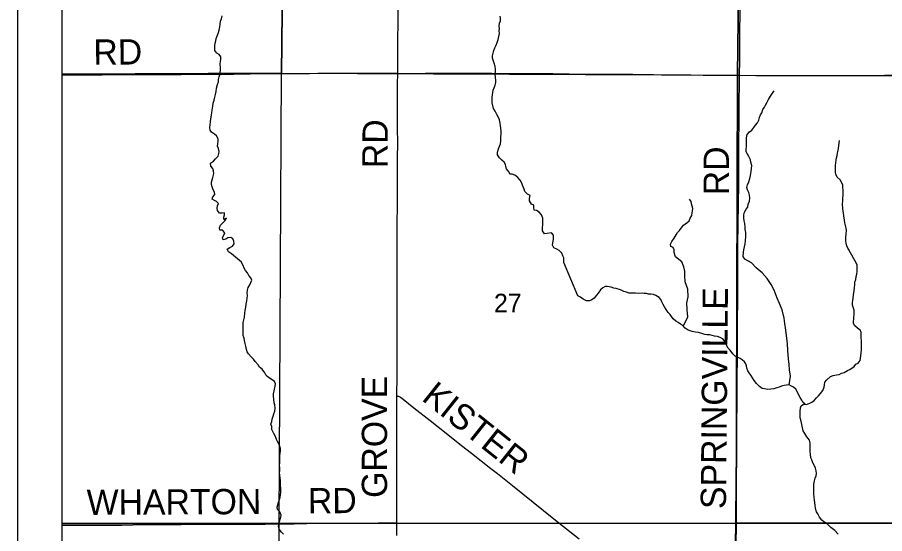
# Model space of a CAD drawing. Extents: x 0 to 34, y 0 to 22.
# Drawn here: x 2 to 3.95, y 16.861 to 18.022 of the extents above; entities that cross this region are included whole.
import ezdxf

# ---------------------------------------------------------------- set-up
doc = ezdxf.new("R2010")
doc.units = 0
for name, color, linetype in [('Default', 7, 'Continuous'), ('GM_X_County_Road', 7, 'Continuous'), ('GM_X_County_Road_Text', 7, 'Continuous'), ('GM_X_Minor_River', 7, 'Continuous'), ('GM_X_Section', 7, 'Continuous'), ('GM_X_Section_Text', 7, 'Continuous'), ('GM_X_State_Route', 7, 'Continuous'), ('GM_X_Township_Road', 7, 'Continuous'), ('GM_X_Township_Road_Text', 7, 'Continuous'), ('SH_Data', 7, 'Continuous')]:
    doc.layers.add(name, color=color, linetype=linetype)

msp = doc.modelspace()

# ---------------------------------------------------------------- linework, layer by layer
at = {"layer": 'Default'}
for points in [[(2.4548, 18.9153), (2.1, 18.9091), (2.1, 17.8937), (2.5938, 17.8965), (2.6002, 18.514), (2.4548, 18.514)], [(2.1, 17.8937), (2.1, 16.8844), (2.5888, 16.8843), (2.5938, 17.8965)], [(2.1, 16.8844), (2.1, 15.87), (2.5857, 15.8713), (2.5888, 16.8843)]]:
    msp.add_lwpolyline(points, close=True, dxfattribs=at)
at = {"layer": 'GM_X_County_Road'}
for points in [[(2.855, 17.896), (2.8551, 17.9234), (2.8554, 17.9703), (2.8559, 18.0107), (2.8562, 18.1102), (2.8563, 18.1288), (2.8567, 18.1597), (2.8569, 18.1752), (2.8573, 18.2095), (2.8578, 18.2498), (2.8579, 18.2683), (2.8581, 18.2828), (2.8581, 18.3026), (2.8579, 18.3181), (2.8579, 18.3492), (2.8581, 18.3742), (2.8598, 18.4422), (2.8601, 18.4603), (2.8603, 18.4764), (2.8608, 18.514)], [(2.8534, 17.1706), (2.8534, 17.1785), (2.8538, 17.2095), (2.8536, 17.225), (2.8536, 17.2581), (2.8535, 17.3023), (2.8537, 17.3672), (2.8538, 17.3924), (2.8537, 17.4546), (2.8539, 17.4856), (2.8538, 17.5355), (2.8539, 17.554), (2.8542, 17.6036), (2.8543, 17.6379), (2.8544, 17.6557), (2.8545, 17.675), (2.8547, 17.7057), (2.855, 17.7383), (2.8549, 17.7739), (2.8548, 17.7959), (2.8548, 17.8179), (2.8548, 17.8521), (2.8549, 17.8708), (2.855, 17.896)], [(2.853, 16.8858), (2.853, 16.8915), (2.853, 16.9299), (2.8532, 16.9549), (2.8531, 16.989), (2.8531, 17.0199), (2.8529, 17.0697), (2.8531, 17.1255), (2.8534, 17.1706)], [(2.853, 16.8571), (2.8531, 16.8789), (2.853, 16.8858)]]:
    msp.add_lwpolyline(points, dxfattribs=at)
at = {"layer": 'GM_X_Minor_River'}
for points in [[(2.4519, 17.9879), (2.4538, 17.9928), (2.4553, 18.0008), (2.4556, 18.0065), (2.4564, 18.013), (2.4586, 18.0183), (2.4601, 18.0248)], [(3.2281, 17.4709), (3.2285, 17.4751), (3.2281, 17.4812), (3.2261, 17.4861), (3.2242, 17.4918), (3.2181, 17.4979), (3.2124, 17.5005), (3.2059, 17.5035), (3.2032, 17.51), (3.2036, 17.5149), (3.2051, 17.5225), (3.205, 17.5324), (3.2008, 17.5373), (3.1913, 17.5358), (3.1853, 17.535), (3.1807, 17.5418), (3.1803, 17.5498), (3.1814, 17.5555), (3.1813, 17.565), (3.1809, 17.5703), (3.1782, 17.5783), (3.1729, 17.584), (3.1668, 17.5877), (3.1618, 17.5885), (3.1611, 17.5942), (3.161, 17.5999), (3.1561, 17.6018), (3.1511, 17.6097), (3.1511, 17.615), (3.1529, 17.6211), (3.1469, 17.6241), (3.1411, 17.6302), (3.1396, 17.6359), (3.1369, 17.6412), (3.1334, 17.6503), (3.13, 17.656), (3.125, 17.6617), (3.1185, 17.667), (3.1121, 17.6692), (3.1068, 17.6692), (3.1056, 17.6741), (3.0999, 17.6813), (3.0983, 17.6863), (3.0972, 17.6912), (3.0941, 17.6961), (3.0888, 17.7007), (3.0838, 17.7064), (3.0796, 17.7128), (3.0796, 17.7189), (3.0818, 17.7261), (3.0863, 17.7376), (3.0866, 17.744), (3.087, 17.7528), (3.0873, 17.7608), (3.0873, 17.7661), (3.0869, 17.7725), (3.0861, 17.7779), (3.0853, 17.7836), (3.0837, 17.7912), (3.0814, 17.7968), (3.078, 17.8037), (3.0741, 17.8109), (3.0703, 17.8169), (3.0672, 17.8299), (3.0672, 17.8352), (3.0675, 17.8424), (3.069, 17.8531), (3.0697, 17.858), (3.072, 17.8633), (3.0738, 17.8694), (3.0753, 17.8751), (3.0753, 17.8801), (3.0745, 17.8877), (3.0741, 17.8938), (3.0748, 17.9006), (3.0748, 17.9056), (3.0744, 17.9113), (3.0721, 17.9185), (3.0682, 17.9299), (3.0682, 17.9356), (3.0693, 17.9413), (3.0711, 17.9474), (3.073, 17.9531), (3.076, 17.9592), (3.0786, 17.9653), (3.0805, 17.9721), (3.082, 17.9786), (3.0835, 17.9858), (3.0834, 17.9915), (3.0838, 17.9968), (3.0834, 18.0022), (3.0841, 18.009), (3.086, 18.014), (3.086, 18.0189), (3.0855, 18.0246)], [(2.5037, 17.4713), (2.4811, 17.4903), (2.4743, 17.4949), (2.4716, 17.5006), (2.478, 17.5048), (2.4833, 17.5074), (2.4875, 17.5124), (2.487, 17.5189), (2.4847, 17.5242), (2.4798, 17.5268), (2.4733, 17.526), (2.4684, 17.5233), (2.4627, 17.5214), (2.4608, 17.5264), (2.4661, 17.5378), (2.4611, 17.5435), (2.455, 17.5434), (2.4542, 17.5484), (2.4565, 17.5545), (2.4614, 17.5591), (2.4667, 17.5648), (2.4701, 17.5701), (2.464, 17.5678), (2.464, 17.5728), (2.4655, 17.5777), (2.4658, 17.5827), (2.4601, 17.5819), (2.4545, 17.5815), (2.4499, 17.5875), (2.4491, 17.5928), (2.4498, 17.5982), (2.4521, 17.6031), (2.4479, 17.608), (2.4429, 17.6103), (2.438, 17.6129), (2.4391, 17.6183), (2.4436, 17.6236), (2.4428, 17.6289), (2.4401, 17.6339), (2.4378, 17.6407), (2.4363, 17.646), (2.4366, 17.6517), (2.4381, 17.6567), (2.4392, 17.662), (2.4415, 17.6708), (2.441, 17.6765), (2.4395, 17.6818), (2.4353, 17.6871), (2.4341, 17.6939), (2.4409, 17.6989), (2.4451, 17.7038), (2.4511, 17.71), (2.453, 17.7157), (2.4533, 17.7206), (2.4522, 17.7267), (2.4502, 17.7324), (2.451, 17.7377), (2.4513, 17.7438), (2.4513, 17.7491), (2.4478, 17.7552), (2.4429, 17.759), (2.4368, 17.7635), (2.4334, 17.7684), (2.4326, 17.7745), (2.4333, 17.7802), (2.4344, 17.7874), (2.4355, 17.7981), (2.4369, 17.8072), (2.4377, 17.8133), (2.4391, 17.8221), (2.4402, 17.8289), (2.4425, 17.8354), (2.4436, 17.8422), (2.4455, 17.8483), (2.4469, 17.8548), (2.448, 17.8628), (2.4499, 17.8712), (2.4518, 17.8769), (2.4525, 17.8822), (2.454, 17.8879), (2.4555, 17.8929), (2.4562, 17.8978), (2.4569, 17.9031), (2.4569, 17.9088), (2.4561, 17.9168), (2.4565, 17.9225), (2.4576, 17.9275), (2.4575, 17.9328), (2.4533, 17.9381), (2.4484, 17.9415), (2.4442, 17.9472), (2.4438, 17.9536), (2.4441, 17.9586), (2.4448, 17.9639), (2.446, 17.9692), (2.4471, 17.9742), (2.4501, 17.9814), (2.4519, 17.9879)], [(3.6506, 17.4701), (3.6355, 17.4782), (3.6318, 17.4842), (3.6322, 17.4937), (3.6333, 17.499), (3.6344, 17.5059), (3.6359, 17.5127), (3.6366, 17.5199), (3.6373, 17.5287), (3.6372, 17.5382), (3.6364, 17.5458), (3.636, 17.5507), (3.6352, 17.5587), (3.6341, 17.5648), (3.6329, 17.5712), (3.6332, 17.5777), (3.6347, 17.5842), (3.6381, 17.5903), (3.6419, 17.5952), (3.643, 17.6017), (3.646, 17.6089), (3.6463, 17.6162), (3.6455, 17.6219), (3.644, 17.6279), (3.6413, 17.6344), (3.6401, 17.6397), (3.6416, 17.645), (3.6442, 17.6523), (3.6465, 17.6595), (3.648, 17.666), (3.6498, 17.6755), (3.6505, 17.682), (3.6509, 17.6888), (3.6489, 17.696), (3.6478, 17.7013), (3.6443, 17.7089), (3.6416, 17.7146), (3.6386, 17.7196), (3.6385, 17.726), (3.6389, 17.731), (3.6392, 17.7363), (3.6392, 17.7511), (3.6403, 17.7587), (3.6459, 17.7648), (3.6508, 17.7683), (3.6557, 17.774), (3.6591, 17.7797), (3.6637, 17.7847), (3.6667, 17.7904), (3.6681, 17.7969), (3.6704, 17.8026), (3.6734, 17.8075), (3.6756, 17.8144), (3.6798, 17.8197), (3.6817, 17.8247), (3.6858, 17.8312), (3.6884, 17.8373), (3.6933, 17.8445), (3.6975, 17.8514), (3.7012, 17.8567)], [(3.8698, 17.4978), (3.8697, 17.4982), (3.867, 17.5031), (3.8647, 17.5081), (3.8632, 17.5134), (3.862, 17.5198), (3.8624, 17.5271), (3.8634, 17.535), (3.8638, 17.5426), (3.863, 17.5483), (3.8615, 17.554), (3.8603, 17.5597), (3.8591, 17.5658), (3.8575, 17.5757), (3.8571, 17.5814), (3.856, 17.5863), (3.8552, 17.592), (3.8551, 17.6027), (3.8555, 17.6088), (3.8558, 17.6152), (3.8562, 17.6225), (3.8561, 17.6335), (3.8557, 17.6392), (3.8557, 17.6445), (3.8534, 17.6498), (3.8495, 17.6566), (3.8427, 17.6627), (3.84, 17.6691), (3.8392, 17.6741), (3.8388, 17.6824), (3.8391, 17.6885), (3.8398, 17.6946), (3.8409, 17.7011), (3.8417, 17.706), (3.8428, 17.7114), (3.8435, 17.7163), (3.8461, 17.7273), (3.8476, 17.7395), (3.8483, 17.7452)], [(3.4797, 17.4836), (3.4762, 17.4933), (3.4762, 17.499), (3.4739, 17.5044), (3.4689, 17.507), (3.4685, 17.5123), (3.4711, 17.518), (3.4768, 17.5257), (3.4809, 17.5329), (3.4839, 17.5379), (3.4881, 17.5428), (3.4918, 17.5478), (3.4975, 17.5547), (3.5051, 17.56), (3.51, 17.5642), (3.5126, 17.5703), (3.516, 17.5768), (3.5171, 17.5821), (3.5174, 17.5871), (3.5182, 17.592), (3.517, 17.5977), (3.5155, 17.6026), (3.5143, 17.608), (3.5109, 17.6133)], [(3.8826, 17.4211), (3.8826, 17.4268), (3.8845, 17.4329), (3.8856, 17.4397), (3.8871, 17.4447), (3.8875, 17.4504), (3.8875, 17.4569), (3.8878, 17.4648), (3.8859, 17.4698), (3.8698, 17.4978)], [(2.5503, 17.231), (2.5446, 17.2352), (2.5412, 17.2405), (2.5347, 17.2485), (2.5308, 17.2534), (2.5259, 17.2588), (2.5197, 17.2652), (2.5167, 17.2702), (2.5151, 17.2755), (2.5136, 17.2827), (2.5124, 17.2888), (2.5109, 17.2957), (2.5097, 17.3006), (2.5078, 17.3067), (2.5078, 17.312), (2.5074, 17.3223), (2.5074, 17.3363), (2.5092, 17.342), (2.5104, 17.3477), (2.5115, 17.3569), (2.5123, 17.3626), (2.5134, 17.3706), (2.5145, 17.3774), (2.516, 17.3846), (2.5168, 17.3907), (2.5171, 17.3968), (2.5167, 17.4025), (2.5171, 17.4086), (2.519, 17.4147), (2.5224, 17.4208), (2.5251, 17.4257), (2.527, 17.431), (2.5251, 17.4363), (2.5201, 17.4413), (2.5174, 17.4478), (2.5128, 17.4531), (2.5101, 17.4584), (2.5078, 17.4637), (2.5047, 17.4694), (2.5037, 17.4713)], [(3.7709, 17.1521), (3.766, 17.1569), (3.7634, 17.1615), (3.7595, 17.1675), (3.7553, 17.1759), (3.7526, 17.1809), (3.7496, 17.1858), (3.7446, 17.1904), (3.74, 17.193), (3.7347, 17.1961), (3.7289, 17.1949), (3.7236, 17.1942), (3.7175, 17.193), (3.7125, 17.1908), (3.7072, 17.1889), (3.7007, 17.187), (3.6935, 17.1858), (3.687, 17.1855), (3.6793, 17.1866), (3.674, 17.1877), (3.6683, 17.1919), (3.6618, 17.1992), (3.6564, 17.2056), (3.6522, 17.2113), (3.6484, 17.2174), (3.6453, 17.2231), (3.6422, 17.2277), (3.6399, 17.233), (3.6388, 17.2383), (3.6376, 17.2429), (3.6349, 17.2479), (3.6296, 17.2524), (3.6246, 17.2547), (3.6189, 17.2577), (3.6139, 17.2604), (3.6086, 17.2657), (3.602, 17.2737), (3.5978, 17.2783), (3.5948, 17.2832), (3.5925, 17.2882), (3.5909, 17.2927), (3.5856, 17.2996), (3.5798, 17.3026), (3.5737, 17.3042), (3.5669, 17.3053), (3.5619, 17.3068), (3.5569, 17.308), (3.5501, 17.3084), (3.5455, 17.3091), (3.539, 17.311), (3.5314, 17.3133), (3.5241, 17.3145), (3.5172, 17.316), (3.5126, 17.3171), (3.5077, 17.3187), (3.5012, 17.3232), (3.4962, 17.3293), (3.4905, 17.3324), (3.4851, 17.3358), (3.4802, 17.3392), (3.4744, 17.3441), (3.4702, 17.3491), (3.4671, 17.3537), (3.4626, 17.3586), (3.4583, 17.3655), (3.4545, 17.3712), (3.4514, 17.3765), (3.4484, 17.3822), (3.4465, 17.3875), (3.4426, 17.3921), (3.4354, 17.397), (3.43, 17.3989), (3.4239, 17.3997), (3.4189, 17.3997), (3.4144, 17.4008), (3.409, 17.4008), (3.4044, 17.4016), (3.3953, 17.4012), (3.3892, 17.4016), (3.3754, 17.4016), (3.3693, 17.4043), (3.3636, 17.4058), (3.3556, 17.4092), (3.346, 17.4123), (3.3411, 17.4131), (3.3346, 17.415), (3.3262, 17.4172), (3.3212, 17.4169), (3.3159, 17.4142), (3.3109, 17.4096), (3.3056, 17.402), (3.3018, 17.3971), (3.2965, 17.391), (3.2911, 17.3872), (3.2858, 17.3849), (3.2797, 17.3846), (3.272, 17.3884), (3.2659, 17.3929), (3.2598, 17.396), (3.2281, 17.4709)], [(3.4972, 17.3281), (3.5068, 17.349), (3.5056, 17.3641), (3.5048, 17.3805), (3.5077, 17.3938), (3.5073, 17.4108), (3.5012, 17.4271), (3.5007, 17.4408), (3.5003, 17.451), (3.498, 17.4609), (3.4938, 17.4723), (3.4797, 17.4836)], [(3.7347, 17.1961), (3.738, 17.215), (3.736, 17.2298), (3.7348, 17.2412), (3.7333, 17.2541), (3.7317, 17.2734), (3.7309, 17.2886), (3.7297, 17.3), (3.7273, 17.3186), (3.7254, 17.3337), (3.7234, 17.3459), (3.7192, 17.3645), (3.7135, 17.3785), (3.7077, 17.3906), (3.7009, 17.4088), (3.6944, 17.4213), (3.6852, 17.4346), (3.6742, 17.4474), (3.6609, 17.4588), (3.6506, 17.4701)], [(3.8454, 16.8606), (3.8373, 16.8682), (3.8285, 16.8755), (3.8213, 16.8827), (3.8132, 16.8876), (3.8083, 16.8918), (3.8033, 16.8987), (3.7995, 16.9059), (3.7964, 16.9105), (3.7941, 16.9177), (3.7933, 16.9257), (3.7921, 16.9367), (3.7914, 16.9424), (3.7906, 16.9519), (3.7902, 16.9607), (3.7902, 16.9664), (3.7905, 16.9725), (3.792, 16.9801), (3.7935, 16.9861), (3.7954, 16.9911), (3.7962, 16.9968), (3.7958, 17.0029), (3.7939, 17.0086), (3.7916, 17.0139), (3.7885, 17.0207), (3.7862, 17.0272), (3.7839, 17.0318), (3.7831, 17.0398), (3.7823, 17.0462), (3.7819, 17.0535), (3.7819, 17.0656), (3.7808, 17.0713), (3.775, 17.0789), (3.77, 17.0862), (3.7662, 17.0923), (3.7639, 17.1033), (3.7619, 17.1139), (3.76, 17.1219), (3.7596, 17.1272), (3.7596, 17.136), (3.7607, 17.1443), (3.7619, 17.1489), (3.7672, 17.1523), (3.7737, 17.1519), (3.7813, 17.155), (3.7859, 17.1569), (3.7908, 17.1603), (3.7962, 17.1664), (3.8011, 17.1713), (3.8057, 17.1766), (3.8103, 17.1835), (3.8133, 17.1907), (3.814, 17.196), (3.8152, 17.2021), (3.8186, 17.2067), (3.8281, 17.2147), (3.8335, 17.2169), (3.8415, 17.2185), (3.8472, 17.2192), (3.8525, 17.2219), (3.8586, 17.2234), (3.8659, 17.2283), (3.8712, 17.2302), (3.8807, 17.2371), (3.8849, 17.2424), (3.8902, 17.2447), (3.8944, 17.2508), (3.8952, 17.2557), (3.8959, 17.2614), (3.8967, 17.2679), (3.8974, 17.2743), (3.8978, 17.2816), (3.8974, 17.2888), (3.8978, 17.296), (3.897, 17.3009), (3.897, 17.3139), (3.8947, 17.3184), (3.8889, 17.323), (3.8828, 17.3283), (3.8797, 17.334), (3.8797, 17.3386), (3.8805, 17.3435), (3.8805, 17.3485), (3.8808, 17.353), (3.8808, 17.3633), (3.8773, 17.3751), (3.8773, 17.3808), (3.8777, 17.3854), (3.8785, 17.3903), (3.8792, 17.3987), (3.8811, 17.407), (3.8818, 17.4135), (3.8826, 17.4211)], [(2.5982, 16.8602), (2.594, 16.8651), (2.5886, 16.8712), (2.5874, 16.8773), (2.5886, 16.8868), (2.5924, 16.8982), (2.5931, 16.9032), (2.5897, 16.9108), (2.5851, 16.9157), (2.5843, 16.9207), (2.5854, 16.9264), (2.5869, 16.9321), (2.5892, 16.9378), (2.5907, 16.9431), (2.5915, 16.948), (2.5926, 16.9545), (2.5922, 16.9636), (2.5918, 16.9693), (2.5914, 16.9758), (2.5918, 16.9811), (2.5906, 16.9872), (2.5898, 16.9925), (2.5895, 16.9979), (2.5902, 17.0028), (2.5898, 17.0089), (2.589, 17.0153), (2.5898, 17.0203), (2.5901, 17.0279), (2.5897, 17.0363), (2.5905, 17.0423), (2.5916, 17.0477), (2.5912, 17.053), (2.5882, 17.0621), (2.5847, 17.0682), (2.5824, 17.0732), (2.5801, 17.0796), (2.5763, 17.0868), (2.5724, 17.0956), (2.572, 17.1021), (2.5701, 17.1074), (2.572, 17.1135), (2.5731, 17.1184), (2.5754, 17.1256), (2.5765, 17.1306), (2.5788, 17.137), (2.5796, 17.1431), (2.5788, 17.1507), (2.5772, 17.1557), (2.5768, 17.1637), (2.5761, 17.1701), (2.5757, 17.1758), (2.5772, 17.1823), (2.5794, 17.1926), (2.5802, 17.1983), (2.5783, 17.2032), (2.5725, 17.207), (2.5645, 17.2127), (2.5595, 17.2165), (2.5565, 17.2226), (2.5503, 17.231)]]:
    msp.add_lwpolyline(points, dxfattribs=at)
at = {"layer": 'GM_X_Section'}
for points in [[(2.6002, 18.514), (2.5938, 17.8965), (3.6191, 17.892), (3.6261, 18.514)], [(3.6261, 18.514), (3.6191, 17.892), (4.6321, 17.8882), (4.6433, 18.514)], [(2.5938, 17.8965), (3.6191, 17.892), (3.6155, 16.8848), (2.5888, 16.8843)], [(3.6191, 17.892), (4.6321, 17.8882), (4.6282, 16.8848), (3.6155, 16.8848)], [(2.5888, 16.8843), (3.6155, 16.8848), (3.6011, 15.8725), (2.5857, 15.8713)], [(3.6155, 16.8848), (4.6282, 16.8848), (4.6171, 15.8766), (3.6166, 15.8725), (3.6011, 15.8725)]]:
    msp.add_lwpolyline(points, close=True, dxfattribs=at)
at = {"layer": 'GM_X_State_Route'}
msp.add_lwpolyline([(5.6507, 20.9), (2.1, 20.9), (2.1, 15.8695)], dxfattribs=at)
at = {"layer": 'GM_X_Township_Road'}
for points in [[(3.6233, 17.8916), (3.6237, 17.9253), (3.624, 17.9843), (3.6246, 18.0372), (3.625, 18.093), (3.6255, 18.152), (3.6257, 18.1769), (3.6263, 18.2235), (3.6267, 18.2545), (3.6267, 18.27), (3.6271, 18.2854), (3.6275, 18.2977), (3.6278, 18.3163), (3.6278, 18.3629), (3.6284, 18.4095), (3.6287, 18.4406), (3.6287, 18.4779), (3.6292, 18.514)], [(2.1, 17.8921), (2.1134, 17.8922), (2.1382, 17.8925), (2.191, 17.8929), (2.2158, 17.8931), (2.2407, 17.8932), (2.2873, 17.8934), (2.3246, 17.8934), (2.3463, 17.8935), (2.3681, 17.8936), (2.4084, 17.894), (2.427, 17.8943), (2.4581, 17.8944), (2.486, 17.8944), (2.5233, 17.8948), (2.5606, 17.8952), (2.5978, 17.8955), (2.6284, 17.8955), (2.657, 17.8957), (2.6754, 17.896), (2.6972, 17.8962), (2.781, 17.8964), (2.7997, 17.8965), (2.8338, 17.8962), (2.855, 17.896)], [(2.855, 17.896), (2.8618, 17.8958), (2.8897, 17.8959), (2.9177, 17.8961), (2.9363, 17.8962), (2.9673, 17.8962), (3.0015, 17.8962), (3.0356, 17.8961), (3.0666, 17.8961), (3.0946, 17.8958), (3.1475, 17.8957), (3.2034, 17.8954), (3.2406, 17.8949), (3.2903, 17.8943), (3.3213, 17.8941), (3.3524, 17.894), (3.3834, 17.8939), (3.4114, 17.8934), (3.43, 17.8932), (3.4735, 17.8929), (3.5139, 17.8923), (3.5419, 17.8919), (3.5978, 17.8916), (3.6233, 17.8916)], [(3.6138, 16.8144), (3.6152, 16.8765), (3.6153, 16.8858), (3.6154, 16.8935), (3.6154, 16.912), (3.6154, 16.9298), (3.6155, 16.9407), (3.6157, 16.9549), (3.6163, 16.9717), (3.6166, 16.9912), (3.617, 17.0255), (3.6169, 17.0469), (3.6171, 17.0593), (3.6174, 17.0935), (3.6181, 17.1711), (3.6183, 17.2052), (3.6184, 17.2238), (3.6185, 17.2456), (3.6186, 17.2611), (3.6185, 17.2797), (3.6185, 17.2983), (3.6186, 17.3106), (3.6188, 17.3292), (3.6196, 17.3975), (3.6198, 17.4379), (3.6198, 17.4534), (3.6197, 17.4907), (3.6199, 17.5093), (3.6206, 17.559), (3.6211, 17.5993), (3.6217, 17.649), (3.6219, 17.6893), (3.6219, 17.7173), (3.622, 17.7297), (3.6221, 17.7545), (3.6224, 17.7732), (3.6226, 17.7949), (3.6227, 17.8197), (3.6228, 17.8352), (3.6231, 17.8694), (3.6233, 17.888), (3.6233, 17.8916)], [(3.6233, 17.8916), (3.66, 17.8913), (3.7066, 17.891), (3.7439, 17.8911), (3.7843, 17.891), (3.8371, 17.891), (3.8713, 17.8912), (3.9179, 17.8913), (3.949, 17.8915), (3.9894, 17.8915), (4.0236, 17.8914), (4.0484, 17.8915), (4.0701, 17.8915), (4.0888, 17.8913), (4.1167, 17.8912), (4.1354, 17.891)], [(2.8534, 17.1706), (2.8557, 17.1706), (2.8568, 17.1705), (2.8584, 17.1699), (2.8609, 17.1684), (2.8671, 17.1638), (2.8914, 17.1445), (2.9281, 17.1157), (2.9499, 17.0983), (2.9792, 17.0752), (2.9986, 17.0598), (3.0206, 17.0426), (3.0643, 17.0079), (3.079, 16.9964), (3.1128, 16.9695), (3.183, 16.9131), (3.2169, 16.886), (3.2629, 16.8494)], [(2.1, 16.8807), (2.12, 16.8806), (2.1541, 16.8802), (2.2099, 16.8803), (2.2348, 16.8807), (2.2596, 16.881), (2.3183, 16.8818), (2.3682, 16.8821), (2.424, 16.8824), (2.4549, 16.8824), (2.5078, 16.8828), (2.5264, 16.8828), (2.5573, 16.8829), (2.5759, 16.8832), (2.5976, 16.8835), (2.6222, 16.8838), (2.6504, 16.884), (2.7186, 16.8847), (2.7528, 16.8851), (2.7869, 16.8852), (2.8117, 16.8855), (2.8272, 16.8858), (2.8457, 16.8858), (2.8485, 16.8858), (2.853, 16.8858)]]:
    msp.add_lwpolyline(points, dxfattribs=at)
at = {"layer": 'SH_Data'}
for p, q in [((2, 21), (2, 14)), ((2.1, 20.9), (2.1, 14.1))]:
    msp.add_line(p, q, dxfattribs=at)

# ---------------------------------------------------------------- texts
at = {"layer": 'GM_X_County_Road_Text'}
for s, rotation, p in [('RD', 89.5099, (2.832, 17.6826)), ('GROVE', 90, (2.8311, 16.9417))]:
    msp.add_text(s, height=0.05682, rotation=rotation, dxfattribs=at).set_placement(p)
at = {"layer": 'GM_X_Section_Text'}
msp.add_text('27', height=0.04186, rotation=0, dxfattribs=at).set_placement((3.0714, 17.3587))
at = {"layer": 'GM_X_Township_Road_Text'}
for s, height, rotation, p in [('RD', 0.05682, 0.4939, (2.1711, 17.9151)), ('RD', 0.05682, 90, (3.5995, 17.6219)), ('SPRINGVILLE', 0.056818, 89.4704, (3.5928, 16.9165)), ('KISTER', 0.05682, 321.459, (2.9066, 17.1627)), ('WHARTON', 0.05682, 0.2681, (2.1559, 16.9035)), ('RD', 0.05682, 0.4936, (2.6533, 16.9068))]:
    msp.add_text(s, height=height, rotation=rotation, dxfattribs=at).set_placement(p)

doc.saveas('drawing.dxf')
